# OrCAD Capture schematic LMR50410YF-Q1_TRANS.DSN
size D; title: LMR50410YF-Q1 SIMPLE SWITCHER® 4-V to 36-V, 1-A Buck; rev: 1.0; note: Datasheet: SLUSDW4      EVM:SLUUC77; note: Synchronous Step Down Converter; note: Converter in SOT-23-6 package
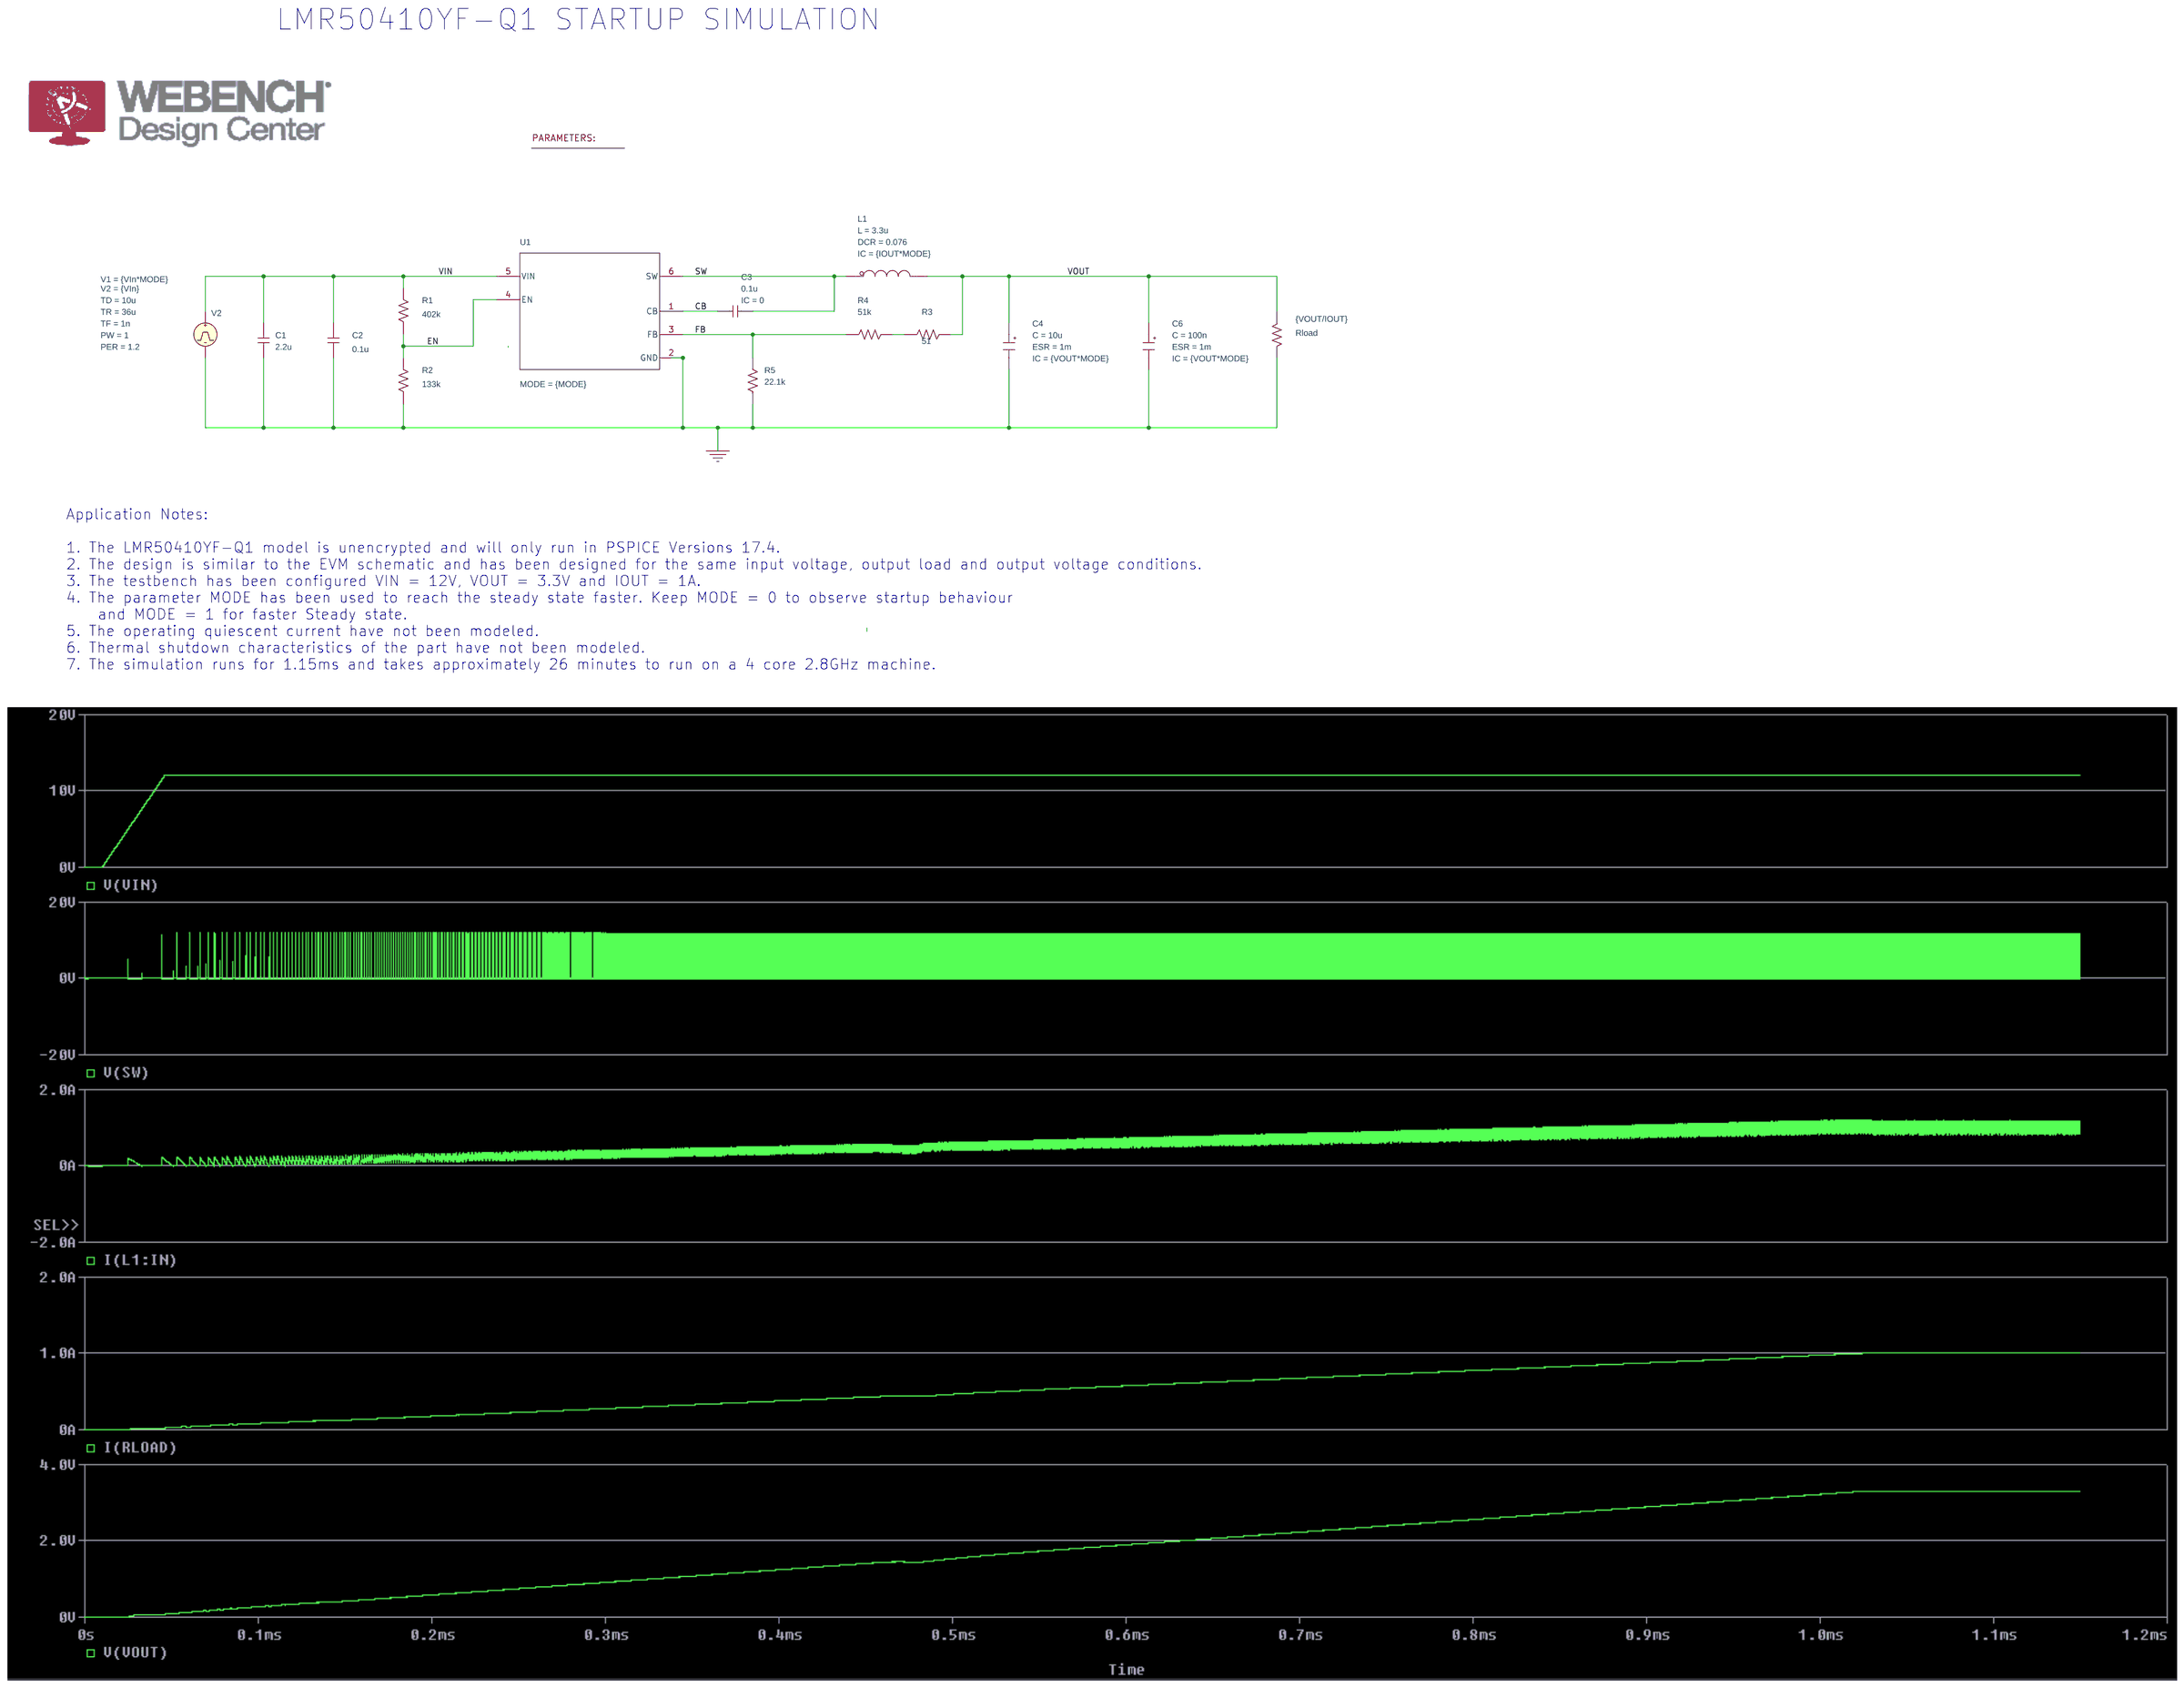
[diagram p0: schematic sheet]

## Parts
1  PARAM
C1  2.2u  [RAD/CK05]
C2  0.1u  [RAD/CK05]
C3  0.1u  [RAD/CK05]
C4  CESR
C6  CESR
L1  LDCR
R1  402k  [AX/RC05]
R2  133k  [AX/RC05]
R3  51  [AX/RC05]
R4  51k  [RC05]
R5  22.1k  [RC05]
Rload  {VOUT/IOUT}  [AX/RC05]
U1  Value  [DBV0006A-IPC_A]
V2  VPULSE

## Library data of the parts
1 = PARAM: MODE: 0; VIn: 12; Vout: 3.3
C1 C2 = C
C3 = C: IC: 0
C4 = CESR_0: C: 10u; ESR: 1m; IC: {VOUT*MODE}; PSpiceTemplate: X^@REFDES %IN %OUT @MODEL PARAMS:  ?C|C=@C||C=100u|  ?ESR|ESR=@ESR||ESR=0.01| ?X|X=@X||X=2|  ?IC|IC=@IC||IC=2|; X: 1
C6 = CESR_0: C: 100n; ESR: 1m; IC: {VOUT*MODE}; PSpiceTemplate: X^@REFDES %IN %OUT @MODEL PARAMS:  ?C|C=@C||C=100u|  ?ESR|ESR=@ESR||ESR=0.01| ?X|X=@X||X=2|  ?IC|IC=@IC||IC=2|; X: 1
L1 = LDCR_0: DCR: 0.076; IC: {IOUT*MODE}; L: 3.3u; PSpiceTemplate: X^@REFDES %IN %OUT @MODEL PARAMS:  ?L|L=@L||L=1u|  ?DCR|DCR=@DCR||DCR=0.01| ?IC|IC=@IC||IC=0|
R1-R5 Rload = R
U1 = LMR50410YF-Q1DBV_TRANS: MODE: {MODE}
V2 = VPULSE: PER: 1.2; PW: 1; TD: 10u; TF: 1n; TR: 36u; V1: {VIn*MODE}; V2: {VIn}

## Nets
VIN: C1.2 C2.2 R1.2 U1.5(VIN) V2.1(+)
0: C1.1 C2.1 C4.3(OUT) C6.3(OUT) R2.1 R5.1 Rload.2 U1.2(GND) V2.2(-)
CB: C3.1 U1.1(CB)
EN: R1.1 R2.2 U1.4(EN)
FB: R4.1 R5.2 U1.3(FB)
SW: C3.2 L1.1(IN) U1.6(SW)
VOUT: C4.1(IN) C6.1(IN) L1.3(OUT) R3.2 Rload.1
N16815413: R3.1 R4.2

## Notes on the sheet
- LMR50410YF-Q1 STARTUP SIMULATION
- Application Notes:
  1. The LMR50410YF-Q1 model is unencrypted and will only run in PSPICE Versions 17.4.
  2. The design is similar to the EVM schematic and has been designed for the same input voltage, output load and output voltage conditions.
  3. The testbench has been configured VIN = 12V, VOUT = 3.3V and IOUT = 1A.
  4. The parameter MODE has been used to reach the steady state faster. Keep MODE = 0 to observe startup behaviour
      and MODE = 1 for faster Steady state.
  5. The operating quiescent current have not been modeled.
  6. Thermal shutdown characteristics of the part have not been modeled.
  7. The simulation runs for 1.15ms and takes approximately 26 minutes to run on a 4 core 2.8GHz machine.
